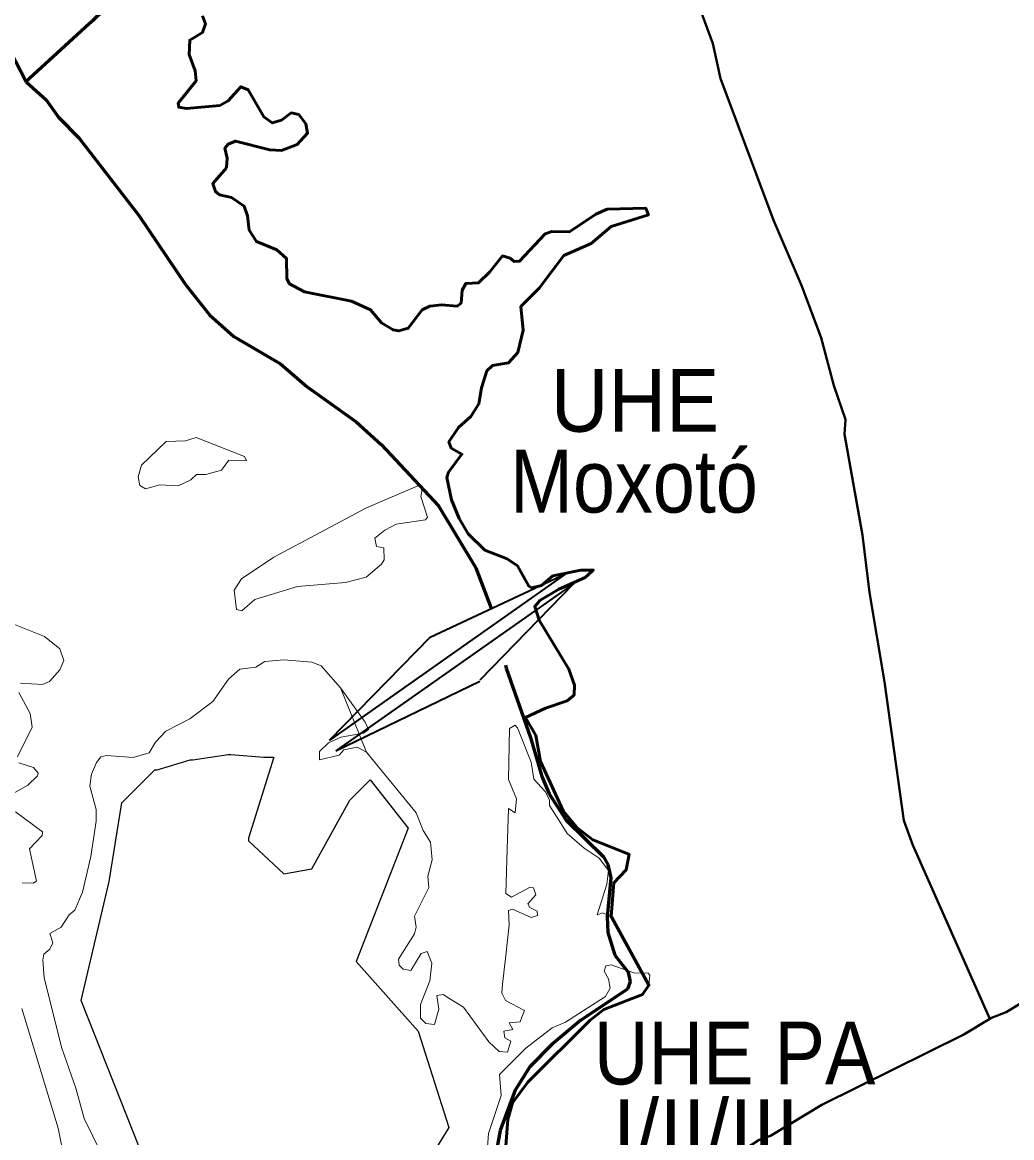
# Model space of a CAD drawing. Extents: x -1643653 to 4543381, y 1624270 to 13878484.
# Drawn here: x 583694 to 591570, y 8960281 to 8969158 of the extents above; entities that cross this region are included whole.
import ezdxf
from ezdxf.enums import TextEntityAlignment as Align

# ---------------------------------------------------------------- set-up
doc = ezdxf.new("R2010")
doc.units = 0
doc.header["$LTSCALE"] = 200
doc.linetypes.add('LONG_DASH_SHORT_DASH', pattern=[9.9, 6, -1.2, 1.5, -1.2])
for name, color, linetype, lineweight in [('12', 7, 'Continuous', 25), ('21', 7, 'Continuous', 25), ('25', 7, 'Continuous', 13), ('59', 7, 'Continuous', 53), ('60', 7, 'Continuous', 13), ('7', 7, 'LONG_DASH_SHORT_DASH', 60)]:
    doc.layers.add(name, color=color, linetype=linetype, lineweight=lineweight)
doc.layers.add('42', color=7, linetype='Continuous')

msp = doc.modelspace()

# ---------------------------------------------------------------- linework, layer by layer
at = {"layer": '12', "lineweight": 40}
for points in [[(588857.5, 8969895.4), (589190.3, 8968987.7), (589251, 8968710.7), (589674.6, 8967582.3), (589899.5, 8967058.9), (590052.2, 8966645.4), (590154.6, 8966267.7), (590247.4, 8965995.5), (590238.8, 8965878.8), (590381.4, 8965077.2), (590437.7, 8964620.9), (590556.9, 8963909.5), (590712.3, 8962804.7), (590781.8, 8962609.4), (591396.4, 8961227.9)], [(587134, 8956453.8), (587843.6, 8957685.7), (587923.7, 8957988.5), (588169.9, 8958625.1), (588237, 8958904.7), (588304.1, 8959099.5), (588468, 8959448.9), (588578.9, 8959635.8), (588673.7, 8959750.1), (588777.5, 8959843.1), (589203.6, 8960089.7), (589393.4, 8960175.8), (589428.5, 8960178.5), (589560.1, 8960264.6), (589648.9, 8960297.2), (590059.4, 8960543.5), (591188.1, 8961101.4), (591408.7, 8961235.4), (591525.3, 8961280.9), (591868.7, 8961488.1), (592154.1, 8961587.2), (592311.1, 8961655)]]:
    msp.add_lwpolyline(points, dxfattribs=at)
at = {"layer": '21'}
msp.add_lwpolyline([(584626.8, 8960201.4), (584162.8, 8961372.1), (584384.7, 8962320.7), (584485.6, 8962946.4), (584747.9, 8963208.8), (584768.1, 8963208.8), (585030.4, 8963289.5), (585050.6, 8963289.5), (585333, 8963329.9), (585353.2, 8963329.9), (585615.5, 8963309.7), (585655.9, 8963309.7), (585676, 8963309.7), (585696.2, 8963309.7), (585494.5, 8962663.8), (585494.5, 8962643.7), (585776.9, 8962381.3), (585998.9, 8962421.6), (586301.5, 8962966.6), (586463, 8963128.1), (586765.6, 8962744.6), (586351.3, 8961682.2), (586846.3, 8961129.9), (587088.5, 8960362.9), (586927, 8960100.5)], dxfattribs=at)
at = {"layer": '25', "lineweight": 35}
for p, q in [((588022.6, 8964770.6), (586135.6, 8963442.6)), ((586940.7, 8964263.4), (588022.6, 8964770.6)), ((588084.7, 8964692), (586189.9, 8963358.5)), ((587339.3, 8963925.5), (588084.7, 8964692)), ((586940.7, 8964263.4), (586135.6, 8963442.6)), ((586189.9, 8963358.5), (587335.7, 8963913.8))]:
    msp.add_line(p, q, dxfattribs=at)
at = {"layer": '25'}
for points in [[(585128.7, 8969210.2), (585151.9, 8969146.5), (585128.6, 8969076.5), (585026.8, 8969016.8), (585022.1, 8968902.1), (585069.3, 8968771.8), (585077.6, 8968692.1), (584933.7, 8968514.1), (584939.8, 8968481.6), (585001.2, 8968471), (585266.9, 8968496.5), (585333.9, 8968534), (585434.5, 8968644.9), (585434.5, 8968644.9), (585492.3, 8968621), (585617.4, 8968405), (585683.3, 8968356.3), (585757.2, 8968379.6), (585833.8, 8968436.8), (585893.9, 8968423.6), (585950.2, 8968348.5), (585965.4, 8968274.1), (585883, 8968184.3), (585757.4, 8968137.5), (585664, 8968141.7), (585392.1, 8968211.7), (585332.8, 8968188.5), (585307.1, 8968156.3), (585324, 8968076.1), (585319.8, 8967999.4)], [(585128.7, 8969210.2), (585151.9, 8969146.5), (585128.6, 8969076.5), (585026.8, 8969016.8), (585022.1, 8968902.1), (585069.3, 8968771.8), (585077.6, 8968692.1), (584933.7, 8968514.1), (584939.8, 8968481.6), (585001.2, 8968471), (585266.9, 8968496.5), (585333.9, 8968534), (585434.5, 8968644.9), (585434.5, 8968644.9), (585492.3, 8968621), (585617.4, 8968405), (585683.3, 8968356.3), (585757.2, 8968379.6), (585833.8, 8968436.8), (585893.9, 8968423.6), (585950.2, 8968348.5), (585965.4, 8968274.1), (585883, 8968184.3), (585757.4, 8968137.5), (585664, 8968141.7), (585392.1, 8968211.7), (585332.8, 8968188.5), (585307.1, 8968156.3), (585324, 8968076.1), (585319.8, 8967999.4)], [(585319.8, 8967999.4), (585209.4, 8967874), (585230.7, 8967810.4), (585264.6, 8967784.9), (585358.3, 8967763.5), (585460, 8967695.5), (585487.7, 8967616.8), (585500.5, 8967502.3), (585557.8, 8967413.1), (585721.3, 8967347.2), (585797.8, 8967276.9), (585799.9, 8967116.4), (585821.7, 8967075), (585940.4, 8967011.6), (586314, 8966937.2), (586464.8, 8966869.3), (586554.2, 8966767.2), (586645.4, 8966710), (586692.1, 8966701.5), (586766.2, 8966722.7), (586877, 8966869.2), (586938.3, 8966898.9), (587031.7, 8966909.6), (587155.3, 8966899.2), (587187, 8966922.6), (587195.6, 8967026.5), (587225.2, 8967079.4), (587325, 8967083.9), (587416.4, 8967171), (587516.5, 8967298.4), (587577.2, 8967281.7), (587609.8, 8967253.9), (587652.2, 8967256), (587856.2, 8967474.6), (587908.7, 8967491.8), (588049.3, 8967489.5), (588259.2, 8967631.5), (588349.7, 8967670.3), (588657.3, 8967677.5), (588667.8, 8967651.8)], [(585319.8, 8967999.4), (585209.4, 8967874), (585230.7, 8967810.4), (585264.6, 8967784.9), (585358.3, 8967763.5), (585460, 8967695.5), (585487.7, 8967616.8), (585500.5, 8967502.3), (585557.8, 8967413.1), (585721.3, 8967347.2), (585797.8, 8967276.9), (585799.9, 8967116.4), (585821.7, 8967075), (585940.4, 8967011.6), (586314, 8966937.2), (586464.8, 8966869.3), (586554.2, 8966767.2), (586645.4, 8966710), (586692.1, 8966701.5), (586766.2, 8966722.7), (586877, 8966869.2), (586938.3, 8966898.9), (587031.7, 8966909.6), (587155.3, 8966899.2), (587187, 8966922.6), (587195.6, 8967026.5), (587225.2, 8967079.4), (587325, 8967083.9), (587416.4, 8967171), (587516.5, 8967298.4), (587577.2, 8967281.7), (587609.8, 8967253.9), (587652.2, 8967256), (587856.2, 8967474.6), (587908.7, 8967491.8), (588049.3, 8967489.5), (588259.2, 8967631.5), (588349.7, 8967670.3), (588657.3, 8967677.5), (588667.8, 8967651.8)], [(588667.8, 8967651.8), (588678.2, 8967626.5), (588381.1, 8967532.1), (588221.7, 8967398.4), (588005.1, 8967300.6), (587807.3, 8967041.3), (587663.1, 8966894.9), (587682, 8966707.8), (587637.4, 8966529.4), (587563.2, 8966446.7), (587438, 8966427.4), (587392.7, 8966384.2), (587348.6, 8966249.6), (587329.2, 8966121.3), (587265.6, 8966019.6), (587165.8, 8965932.5), (587089.5, 8965818), (587106.5, 8965769), (587193.3, 8965719.9), (587087.2, 8965577.5), (587074.5, 8965534.6), (587110.7, 8965356.6), (587170.4, 8965207.5), (587244.3, 8965087.2), (587376.1, 8964957.5), (587554.3, 8964887.4), (587635.2, 8964832.1), (587726.7, 8964670.8), (587750.6, 8964658), (587826.4, 8964675), (587917.9, 8964751.3), (588138.8, 8964796.3), (588239.8, 8964798.6), (588239.8, 8964798.6), (588231, 8964790.9)], [(588667.8, 8967651.8), (588678.2, 8967626.5), (588381.1, 8967532.1), (588221.7, 8967398.4), (588005.1, 8967300.6), (587807.3, 8967041.3), (587663.1, 8966894.9), (587682, 8966707.8), (587637.4, 8966529.4), (587563.2, 8966446.7), (587438, 8966427.4), (587392.7, 8966384.2), (587348.6, 8966249.6), (587329.2, 8966121.3), (587265.6, 8966019.6), (587165.8, 8965932.5), (587089.5, 8965818), (587106.5, 8965769), (587193.3, 8965719.9), (587087.2, 8965577.5), (587074.5, 8965534.6), (587110.7, 8965356.6), (587170.4, 8965207.5), (587244.3, 8965087.2), (587376.1, 8964957.5), (587554.3, 8964887.4), (587635.2, 8964832.1), (587678.5, 8964757.6)], [(588231, 8964790.9), (588174.2, 8964740.5), (587964.7, 8964647.4), (587813.9, 8964556), (587773.6, 8964509.6), (587809.5, 8964400.9), (588045.3, 8964009.8), (588090.5, 8963883.4), (588087.9, 8963805.8), (588079.5, 8963798.7)], [(587773.6, 8964509.6), (587809.5, 8964400.9), (588045.3, 8964009.8), (588090.5, 8963883.4), (588087.9, 8963805.8), (588079.5, 8963798.7)], [(583680, 8963897.4), (583854.1, 8963889), (583909.5, 8963912.6), (583992, 8964005.7), (584023.8, 8964077.5), (583992.3, 8964171.2), (583871.3, 8964269), (583632.9, 8964364.8)], [(583680, 8963897.4), (583854.1, 8963889), (583909.5, 8963912.6), (583992, 8964005.7), (584023.8, 8964077.5), (583992.3, 8964171.2), (583871.3, 8964269), (583632.9, 8964364.8)], [(587098.4, 8961386.8), (587045, 8961420.4), (586993.8, 8961411.8), (587008.6, 8961303.5), (586976.2, 8961182.7), (586906.7, 8961189.1), (586864.3, 8961233.5), (586864.2, 8961341.7), (586938.6, 8961529.2), (586953.1, 8961669.7), (586916.8, 8961762.6), (586868.3, 8961747.5), (586787.2, 8961611.7), (586725.9, 8961622.5), (586694.3, 8961654.3), (586687.9, 8961700.7), (586815.2, 8961902.8), (586830.2, 8961956.5), (586815.4, 8962043.2), (586930, 8962273.3), (586921.5, 8962361.5), (586957.6, 8962493.3), (586943, 8962632.7), (586885.4, 8962727), (586830, 8962867.4), (586432.9, 8963349.4), (586358.6, 8963389.7), (586254.6, 8963368.5), (586216.2, 8963326.1), (586059.1, 8963288.1), (586058.9, 8963353.2), (586131.1, 8963423.6), (586229.2, 8963469.6), (586410.8, 8963500), (586449.8, 8963530), (586424.4, 8963587.3), (586226.9, 8963861.3), (586073.9, 8964035.5), (585999.3, 8964065.2), (585774.7, 8964084.4), (585623.6, 8964071.6), (585553.5, 8964025), (585426.1, 8964010), (585334.9, 8963929.5), (585211.3, 8963752.8), (585026.9, 8963615.1), (584835.5, 8963515.1), (584755, 8963428.2), (584703.5, 8963345.2), (584575.7, 8963306.9), (584575.7, 8963306.9), (584367.9, 8963323.8), (584319.4, 8963311.1), (584283.8, 8963267.3), (584244.9, 8963172.8), (584232.2, 8963079.6), (584283.2, 8962892.7), (584283.2, 8962799.2), (584240.7, 8962518.8), (584172.1, 8962236.3), (584113.2, 8962091.9), (584066.4, 8962055.5), (584002.7, 8961956), (583913.8, 8961907.2), (583936.8, 8961830.6), (583913.5, 8961781.7), (583866.6, 8961740.8), (583856.2, 8961694.6), (583869, 8961554.4), (584009.2, 8960993.4), (584121.2, 8960674.7), (584187.7, 8960432.6), (584325.6, 8960152.6)], [(587098.4, 8961386.8), (587045, 8961420.4), (586993.8, 8961411.8), (587008.6, 8961303.5), (586976.2, 8961182.7), (586906.7, 8961189.1), (586864.3, 8961233.5), (586864.2, 8961341.7), (586938.6, 8961529.2), (586953.1, 8961669.7), (586916.8, 8961762.6), (586868.3, 8961747.5), (586787.2, 8961611.7), (586725.9, 8961622.5), (586694.3, 8961654.3), (586687.9, 8961700.7), (586815.2, 8961902.8), (586830.2, 8961956.5), (586815.4, 8962043.2), (586930, 8962273.3), (586921.5, 8962361.5), (586957.6, 8962493.3), (586943, 8962632.7), (586885.4, 8962727), (586830, 8962867.4), (586432.9, 8963349.4), (586226.9, 8963861.3), (586073.9, 8964035.5), (585999.3, 8964065.2), (585774.7, 8964084.4), (585623.6, 8964071.6), (585553.5, 8964025), (585426.1, 8964010), (585334.9, 8963929.5), (585211.3, 8963752.8), (585026.9, 8963615.1), (584835.5, 8963515.1), (584755, 8963428.2), (584703.5, 8963345.2), (584575.7, 8963306.9), (584575.7, 8963306.9), (584367.9, 8963323.8), (584319.4, 8963311.1), (584283.8, 8963267.3), (584244.9, 8963172.8), (584232.2, 8963079.6), (584283.2, 8962892.7), (584283.2, 8962799.2), (584240.7, 8962518.8), (584172.1, 8962236.3), (584113.2, 8962091.9), (584066.4, 8962055.5), (584002.7, 8961956), (583913.8, 8961907.2), (583936.8, 8961830.6), (583913.5, 8961781.7), (583866.6, 8961740.8), (583856.2, 8961694.6), (583869, 8961554.4), (584009.2, 8960993.4), (584121.2, 8960674.7), (584187.7, 8960432.6), (584325.6, 8960152.6)], [(583654.7, 8963312.4), (583773.3, 8963547.2), (583756.3, 8963657.4), (583667.3, 8963822.9)], [(583654.7, 8963312.4), (583773.3, 8963547.2), (583756.3, 8963657.4), (583667.3, 8963822.9)], [(588079.5, 8963798.7), (588030.2, 8963757.2), (587858.5, 8963700), (587699.1, 8963625.3), (587781.9, 8963483), (587820, 8963275.3), (588002, 8962877.1), (588002, 8962877.1), (588108.8, 8962750.5), (588236.2, 8962650.7), (588523, 8962536.8)], [(588079.5, 8963798.7), (588030.2, 8963757.2), (587858.5, 8963700), (587699.1, 8963625.3), (587781.9, 8963483), (587820, 8963275.3), (588002, 8962877.1), (588002, 8962877.1), (588108.8, 8962750.5), (588236.2, 8962650.7), (588523, 8962536.8)], [(587982.8, 8962779.3), (587890.3, 8962924.4), (587890.1, 8962969.1), (587856.3, 8963036.9), (587766.9, 8963135.1), (587743.6, 8963270.8), (587637.1, 8963543.2), (587617, 8963563.8), (587571.7, 8963538.4), (587565.1, 8963131.3), (587628.8, 8962977.9), (587616.1, 8962866.9), (587565.4, 8962902.1), (587554.1, 8962576.4)], [(587982.8, 8962779.3), (587890.3, 8962924.4), (587890.1, 8962969.1), (587856.3, 8963036.9), (587766.9, 8963135.1), (587743.6, 8963270.8), (587637.1, 8963543.2), (587617, 8963563.8), (587571.7, 8963538.4), (587565.1, 8963131.3), (587628.8, 8962977.9), (587616.1, 8962866.9), (587565.4, 8962902.1), (587554.1, 8962576.4)], [(583548.2, 8962977.4), (583737.5, 8963086.2), (583815.2, 8963159.7), (583820, 8963181), (583784.2, 8963226), (583667.3, 8963264.5)], [(583548.2, 8962977.4), (583737.5, 8963086.2), (583815.2, 8963159.7), (583820, 8963181), (583784.2, 8963226), (583667.3, 8963264.5)], [(583692.8, 8962310.5), (583781.6, 8962306.4), (583807.2, 8962323.5), (583752.2, 8962580.2), (583853.2, 8962685.6), (583854, 8962716.3), (583639.8, 8962873.4)], [(583692.8, 8962310.5), (583781.6, 8962306.4), (583807.2, 8962323.5), (583752.2, 8962580.2), (583853.2, 8962685.6), (583854, 8962716.3), (583639.8, 8962873.4)], [(588354.5, 8962361.1), (588359.4, 8962408.8), (588285.5, 8962505.9), (588167, 8962584.2), (588032.3, 8962701.8), (587982.8, 8962779.3)], [(588354.5, 8962361.1), (588359.4, 8962408.8), (588285.5, 8962505.9), (588167, 8962584.2), (588032.3, 8962701.8), (587982.8, 8962779.3)], [(587554.1, 8962576.4), (587541.8, 8962223.9), (587588.7, 8962196), (587730.7, 8962272.2), (587762.7, 8962269), (587781.7, 8962215.1)], [(587554.1, 8962576.4), (587541.8, 8962223.9), (587588.7, 8962196), (587730.7, 8962272.2), (587762.7, 8962269), (587781.7, 8962215.1)], [(588523, 8962536.8), (588524.4, 8962536.2), (588501.9, 8962412.8), (588402.2, 8962308.3), (588381.1, 8962040.8), (588376.4, 8962042.8)], [(588523, 8962536.8), (588524.4, 8962536.2), (588501.9, 8962412.8), (588402.2, 8962308.3), (588381.1, 8962040.8), (588376.4, 8962042.8)], [(588271.6, 8962055.8), (588270.1, 8962055.2), (588348.1, 8962299.3), (588354.5, 8962361.1)], [(588271.6, 8962055.8), (588270.1, 8962055.2), (588348.1, 8962299.3), (588354.5, 8962361.1)], [(587781.7, 8962215.1), (587781.7, 8962215.1), (587718.2, 8962140.9), (587735, 8962113.3), (587792.4, 8962083.3), (587794.6, 8962050), (587745.5, 8962032.4), (587597.2, 8962100.2), (587563.1, 8962089.5), (587569.5, 8961975.7), (587540.2, 8961707.3), (587517.7, 8961501.6)], [(587781.7, 8962215.1), (587781.7, 8962215.1), (587718.2, 8962140.9), (587735, 8962113.3), (587792.4, 8962083.3), (587794.6, 8962050), (587745.5, 8962032.4), (587597.2, 8962100.2), (587563.1, 8962089.5), (587569.5, 8961975.7), (587540.2, 8961707.3), (587517.7, 8961501.6)], [(588376.4, 8962042.8), (588311.2, 8962069.4), (588271.6, 8962055.8), (588271.7, 8962060.3), (588271.6, 8962055.8)], [(588376.4, 8962042.8), (588311.2, 8962069.4), (588271.6, 8962055.8), (588271.7, 8962060.3), (588271.6, 8962055.8)], [(587541.6, 8960215), (587558.8, 8960425), (587596.7, 8960558.6), (587717.4, 8960723.2), (588213.5, 8961217.2), (588323.7, 8961300.9), (588630.6, 8961421.7), (588681.9, 8961493.8), (588689.2, 8961575.7), (588675.2, 8961590.7), (588561, 8961592.8), (588381.1, 8961656.2), (588338.6, 8961648.6), (588325.4, 8961606.6), (588359, 8961544.8), (588373.9, 8961471.3), (588335.7, 8961403.9), (588018, 8961201.6), (587911.6, 8961156.7), (587701, 8960992.4), (587493.3, 8960783.2), (587506.9, 8960616.2), (587403.7, 8960314.5), (587373.8, 8959887.7)], [(587517.7, 8961501.6), (587510, 8961431.2), (587539.9, 8961371.6), (587692.7, 8961292.6), (587670.8, 8961239.2)], [(587517.7, 8961501.6), (587510, 8961431.2), (587539.9, 8961371.6), (587692.7, 8961292.6), (587670.8, 8961239.2)], [(587670.8, 8961239.2), (587656.4, 8961204.1), (587570.6, 8961194.6), (587599.2, 8961141.8), (587527.1, 8961129.4), (587535.4, 8961074.6), (587582.5, 8961050.1), (587556.1, 8960961.2), (587491.1, 8960968.1), (587408.1, 8961044.4), (587205.3, 8961319.5), (587098.4, 8961386.8)], [(587670.8, 8961239.2), (587656.4, 8961204.1), (587570.6, 8961194.6), (587599.2, 8961141.8), (587527.1, 8961129.4), (587535.4, 8961074.6), (587582.5, 8961050.1), (587556.1, 8960961.2), (587491.1, 8960968.1), (587408.1, 8961044.4), (587205.3, 8961319.5), (587098.4, 8961386.8)], [(584055.9, 8959969.5), (583979.3, 8960356.6), (583690.5, 8961308.2)], [(584055.9, 8959969.5), (583979.3, 8960356.6), (583690.5, 8961308.2)]]:
    msp.add_lwpolyline(points, dxfattribs=at)
for points in [[(585077.7, 8965854), (584992.7, 8965826.3), (584839.9, 8965820.3), (584642.3, 8965632.9), (584616.8, 8965540.1), (584629.5, 8965471.6), (584675.9, 8965446), (584789, 8965475.7), (584933.4, 8965469.6), (585035.3, 8965516.3), (585079.8, 8965558.5), (585154.1, 8965558.7), (585279.1, 8965592.6), (585337.4, 8965673.5), (585478.9, 8965666.9), (585463.8, 8965703.2)], [(585077.7, 8965854), (584992.7, 8965826.3), (584839.9, 8965820.3), (584642.3, 8965632.9), (584616.8, 8965540.1), (584629.5, 8965471.6), (584675.9, 8965446), (584789, 8965475.7), (584933.4, 8965469.6), (585035.3, 8965516.3), (585079.8, 8965558.5), (585154.1, 8965558.7), (585279.1, 8965592.6), (585337.4, 8965673.5), (585478.9, 8965666.9), (585463.8, 8965703.2)], [(585439, 8964728.2), (585379.4, 8964639), (585398.5, 8964484), (585440.9, 8964473.3), (585545, 8964564.5), (585884.6, 8964666.3), (586267.5, 8964700.5), (586430.8, 8964740.8), (586553.9, 8964845), (586575.2, 8964881), (586570.7, 8964976.5), (586513.6, 8964985.3), (586501.3, 8965053.3), (586579.7, 8965116.9), (586670.6, 8965163.4), (586903.9, 8965197.4), (586919.2, 8965218.6), (586866.7, 8965384.8), (586876.8, 8965441.6), (586860, 8965477.5), (586435.1, 8965293.1), (585696.3, 8964900.4)], [(585439, 8964728.2), (585379.4, 8964639), (585398.5, 8964484), (585440.9, 8964473.3), (585545, 8964564.5), (585884.6, 8964666.3), (586267.5, 8964700.5), (586430.8, 8964740.8), (586553.9, 8964845), (586575.2, 8964881), (586570.7, 8964976.5), (586513.6, 8964985.3), (586501.3, 8965053.3), (586579.7, 8965116.9), (586670.6, 8965163.4), (586903.9, 8965197.4), (586919.2, 8965218.6), (586866.7, 8965384.8), (586876.8, 8965441.6), (586860, 8965477.5), (586435.1, 8965293.1), (585696.3, 8964900.4)]]:
    msp.add_lwpolyline(points, close=True, dxfattribs=at)
at = {"layer": '59'}
for points in [[(585128.7, 8969210.2), (585151.9, 8969146.5), (585128.6, 8969076.5), (585026.8, 8969016.8), (585022.1, 8968902.1), (585069.3, 8968771.8), (585077.6, 8968692.1), (584933.7, 8968514.1), (584939.8, 8968481.6), (585001.2, 8968471), (585266.9, 8968496.5), (585333.9, 8968534), (585434.5, 8968644.9), (585434.5, 8968644.9), (585492.3, 8968621), (585617.4, 8968405), (585683.3, 8968356.3), (585757.2, 8968379.6), (585833.8, 8968436.8), (585893.9, 8968423.6), (585950.2, 8968348.5), (585965.4, 8968274.1), (585883, 8968184.3), (585757.4, 8968137.5), (585664, 8968141.7), (585392.1, 8968211.7), (585332.8, 8968188.5), (585307.1, 8968156.3), (585324, 8968076.1), (585319.8, 8967999.4)], [(585319.8, 8967999.4), (585209.4, 8967874), (585230.7, 8967810.4), (585264.6, 8967784.9), (585358.3, 8967763.5), (585460, 8967695.5), (585487.7, 8967616.8), (585500.5, 8967502.3), (585557.8, 8967413.1), (585721.3, 8967347.2), (585797.8, 8967276.9), (585799.9, 8967116.4), (585821.7, 8967075), (585940.4, 8967011.6), (586314, 8966937.2), (586464.8, 8966869.3), (586554.2, 8966767.2), (586645.4, 8966710), (586692.1, 8966701.5), (586766.2, 8966722.7), (586877, 8966869.2), (586938.3, 8966898.9), (587031.7, 8966909.6), (587155.3, 8966899.2), (587187, 8966922.6), (587195.6, 8967026.5), (587225.2, 8967079.4), (587325, 8967083.9), (587416.4, 8967171), (587516.5, 8967298.4), (587577.2, 8967281.7), (587609.8, 8967253.9), (587652.2, 8967256), (587856.2, 8967474.6), (587908.7, 8967491.8), (588049.3, 8967489.5), (588259.2, 8967631.5), (588349.7, 8967670.3), (588657.3, 8967677.5), (588667.8, 8967651.8)], [(588667.8, 8967651.8), (588678.2, 8967626.5), (588381.1, 8967532.1), (588221.7, 8967398.4), (588005.1, 8967300.6), (587807.3, 8967041.3), (587663.1, 8966894.9), (587682, 8966707.8), (587637.4, 8966529.4), (587563.2, 8966446.7), (587438, 8966427.4), (587392.7, 8966384.2), (587348.6, 8966249.6), (587329.2, 8966121.3), (587265.6, 8966019.6), (587165.8, 8965932.5), (587089.5, 8965818), (587106.5, 8965769), (587193.3, 8965719.9), (587087.2, 8965577.5), (587074.5, 8965534.6), (587110.7, 8965356.6), (587170.4, 8965207.5), (587244.3, 8965087.2), (587376.1, 8964957.5), (587554.3, 8964887.4), (587635.2, 8964832.1), (587726.7, 8964670.8), (587750.6, 8964658), (587826.4, 8964675), (587917.9, 8964751.3), (588138.8, 8964796.3), (588239.8, 8964798.6), (588239.8, 8964798.6), (588231, 8964790.9)], [(588231, 8964790.9), (588174.2, 8964740.5), (587964.7, 8964647.4), (587813.9, 8964556), (587773.6, 8964509.6), (587809.5, 8964400.9), (588045.3, 8964009.8), (588090.5, 8963883.4), (588087.9, 8963805.8), (588079.5, 8963798.7)], [(588079.5, 8963798.7), (588030.2, 8963757.2), (587858.5, 8963700), (587699.1, 8963625.3), (587781.9, 8963483), (587820, 8963275.3), (588002, 8962877.1), (588002, 8962877.1), (588108.8, 8962750.5), (588236.2, 8962650.7), (588523, 8962536.8)], [(588523, 8962536.8), (588524.4, 8962536.2), (588501.9, 8962412.8), (588402.2, 8962308.3), (588381.1, 8962040.8), (588373.5, 8962049.1)], [(588373.5, 8962049.1), (588387.5, 8962034), (588681.9, 8961493.8), (588630.6, 8961421.7), (588323.7, 8961300.9), (588213.5, 8961217.2), (587717.4, 8960723.2), (587596.7, 8960558.6), (587558.8, 8960425), (587541.6, 8960215), (587437, 8959830.7), (587368.2, 8959365.5)]]:
    msp.add_lwpolyline(points, dxfattribs=at)
at = {"layer": '60', "lineweight": 25}
msp.add_spline([(814781, 9009175.5), (814787.2, 9009173.4), (814796.9, 9009173.4), (814799.4, 9009172.4), (814805.1, 9009174.5), (814805.6, 9009176.5), (814811.7, 9009179.5), (814811.7, 9009179.5), (814801.5, 9009181), (814790.7, 9009181.5), (814784.1, 9009183.1), (814777.4, 9009185.1), (814778.4, 9009175.5)], degree=3, dxfattribs=at)
at = {"layer": '7'}
for points in [[(583174.4, 8969966), (583327.9, 8969505.4), (583474.7, 8969160.4), (583725.5, 8968684.8), (583883.2, 8968539.9), (583982.9, 8968403.5), (584146.9, 8968235.1), (584624.8, 8967616.6), (584992.2, 8967072.1), (585186.8, 8966825.7), (585377.2, 8966655.9), (585748.8, 8966438.6), (585960.5, 8966257.3), (586351.6, 8965976.8), (586551, 8965796.4), (587006.6, 8965310.9), (587303.1, 8964815.2), (587426.7, 8964495.3)], [(587540.9, 8964040.5), (587545.5, 8964019), (587739.9, 8963466), (587828.5, 8963155), (587886.8, 8963016.8), (588023, 8962809.1), (588321.3, 8962515.1), (588353.7, 8962454.8), (588379.7, 8962350), (588349.5, 8962039.7), (588356.1, 8961913.4), (588409.9, 8961732.7), (588515.9, 8961598.5), (588533, 8961520.2), (588511.4, 8961464.3), (588140, 8961216), (587908.2, 8961023.1), (587733.4, 8960846.2), (587616.5, 8960660), (587498.3, 8960337.4), (587362.2, 8959603), (587314, 8959147.2), (587303.2, 8958935.8), (587310.7, 8958873)]]:
    msp.add_lwpolyline(points, dxfattribs=at)
msp.add_spline([(583719.8, 8968683.1), (584226, 8969147.1), (585263.8, 8970159.6), (585803.8, 8970817.7), (586453.4, 8971391.4), (587077.8, 8971939.8), (587744.3, 8972277.3), (588469.9, 8972403.9), (588728.8, 8972391.8)], degree=3, dxfattribs=at)

# ---------------------------------------------------------------- texts
at = {"layer": '42'}
for s, width, p in [('UHE', 0.95, (588571.1, 8965899.4)), ('Moxotó', 0.9, (588562.6, 8965256.2)), ('UHE PA', 0.9, (589364.5, 8960705))]:
    msp.add_text(s, height=500, dxfattribs=dict(at, width=width)).set_placement(p, align=Align.CENTER)
msp.add_text('I/II/III', height=500, dxfattribs=at).set_placement((589134.4, 8960086.2), align=Align.CENTER)

doc.saveas('drawing.dxf')
